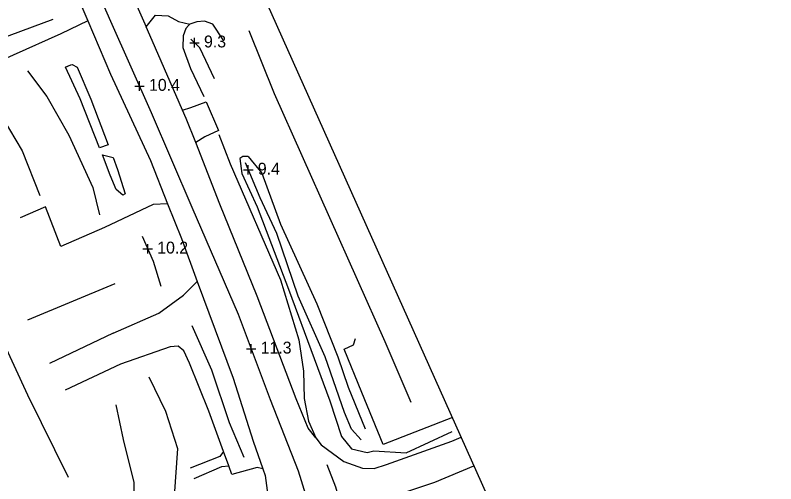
# Model space of a CAD drawing. Extents: x 2316231 to 2323598, y 363169 to 371906.
# Drawn here: x 2320994.3 to 2321314.7, y 364294.4 to 364491.7 of the extents above; entities that cross this region are included whole.
import ezdxf

# ---------------------------------------------------------------- set-up
doc = ezdxf.new("R2010")
doc.units = 0
for name, color, linetype in [('RD_DTM_BkLn1', 7, 'Continuous'), ('RD_DTM_TinHull', 7, 'Continuous'), ('RD_DTM_Void', 7, 'Continuous'), ('RD_EX_H2O', 7, 'Continuous'), ('RD_EX_Road', 7, 'Continuous')]:
    doc.layers.add(name, color=color, linetype=linetype)

msp = doc.modelspace()

# ---------------------------------------------------------------- linework, layer by layer
at = {"layer": 'RD_DTM_BkLn1'}
for p, q in [((2321036.254, 364378.524), (2320999.521, 364363.308)), ((2321035.573, 364357.804), (2321008.797, 364345.053)), ((2321038.693, 364344.812), (2321015.374, 364333.841))]:
    msp.add_line(p, q, dxfattribs=at)
for points in [[(2321019.52, 364523.148), (2321034.445, 364489.194), (2321051.599, 364450.752), (2321068.634, 364410.847), (2321088.233, 364365.793), (2321101.675, 364329.85), (2321113.518, 364299.79), (2321123.854, 364266.312), (2321127.765, 364245.259), (2321131.886, 364230.072), (2321137.453, 364206.087), (2321148.106, 364163.126), (2321158.282, 364114.755), (2321167.432, 364069.646)], [(2321010.188, 364489.799), (2320987.685, 364481.529), (2320972.647, 364474.751), (2320959.282, 364467.553), (2320948.373, 364463.615), (2320932.859, 364456.832), (2320927.564, 364454.539)], [(2321092.764, 364485.212), (2321103.411, 364458.659), (2321150.006, 364354.244), (2321160.92, 364328.735)], [(2320999.467, 364468.176), (2321007.551, 364457.429), (2321016.882, 364441.161), (2321026.969, 364419.106), (2321029.731, 364407.632)], [(2320981.896, 364460.068), (2320989.21, 364448.011), (2320997.168, 364434.55), (2321004.673, 364415.715)], [(2321092.46, 364432.146), (2321090.186, 364432.158), (2321088.852, 364431.393), (2321089.812, 364425.007), (2321096.237, 364410.976), (2321109.343, 364376.383), (2321120.198, 364347.124), (2321126.839, 364329.374), (2321131.736, 364314.306), (2321135.954, 364309.144), (2321142.573, 364307.564), (2321145.347, 364308.283), (2321158.932, 364307.428), (2321178.289, 364316.354)], [(2321092.46, 364432.146), (2321098.137, 364425.104), (2321106.018, 364403.678), (2321121.391, 364370.158), (2321130.222, 364347.777), (2321134.478, 364335.125), (2321141.718, 364317.592)], [(2320956.7, 364411.963), (2320969.866, 364394.944), (2320988.735, 364355.023), (2320999.519, 364331.909), (2321016.624, 364297.206)], [(2321047.821, 364398.681), (2321052.371, 364388.072), (2321055.577, 364377.603)], [(2321068.714, 364361.002), (2321076.973, 364342.429), (2321084.462, 364320.236), (2321090.58, 364305.601)], [(2321050.527, 364339.364), (2321057.529, 364324.907), (2321062.702, 364309.204), (2321061.198, 364289.188), (2321057.459, 364275.41)], [(2321036.709, 364327.601), (2321039.72, 364312.992), (2321044.201, 364294.954), (2321044.105, 364277.357)], [(2321125.55, 364302.496), (2321129.132, 364293.176), (2321132.928, 364280.066), (2321137.461, 364266.076), (2321140.912, 364255.306)], [(2321141.653, 364285.205), (2321171.004, 364295.118), (2321187.507, 364301.942)]]:
    msp.add_lwpolyline(points, dxfattribs=at)
at = {"layer": 'RD_DTM_TinHull'}
msp.add_lwpolyline([(2320809.363, 365353.877), (2320991.706, 364942.038), (2321080.196, 364541.654), (2321314.653, 364017.924), (2320828.919, 363723.372), (2320765.1, 363867.546), (2320638.089, 364094.01), (2320532.322, 364258.493), (2320402.792, 364459.125), (2320263.728, 364603.235), (2320177.718, 364755.167), (2319998.644, 364909.111), (2319975.332, 365147.552), (2319890.016, 365354.444)], dxfattribs=at)
at = {"layer": 'RD_DTM_Void'}
for p, q in [((2321069.812, 364478.095), (2321069.812, 364482.095)), ((2321067.812, 364480.095), (2321071.812, 364480.095)), ((2321044.654, 364461.834), (2321048.654, 364461.834)), ((2321046.654, 364459.834), (2321046.654, 364463.834)), ((2321090.485, 364426.535), (2321094.485, 364426.535)), ((2321092.485, 364424.535), (2321092.485, 364428.535)), ((2321050.114, 364391.335), (2321050.114, 364395.335)), ((2321048.114, 364393.335), (2321052.114, 364393.335)), ((2321093.68, 364349.227), (2321093.68, 364353.227)), ((2321091.68, 364351.227), (2321095.68, 364351.227))]:
    msp.add_line(p, q, dxfattribs=at)
at = {"layer": 'RD_EX_H2O'}
msp.add_line((2321068.365, 364481.468), (2321068.309, 364481.521), dxfattribs=at)
for points in [[(2321078.17, 364464.864), (2321072.11, 364477.914), (2321068.365, 364481.468)], [(2321140.062, 364312.95), (2321135.928, 364317.432), (2321132.929, 364324.397), (2321124.781, 364347.815), (2321113.511, 364373.389), (2321104.47, 364399.821), (2321097.498, 364414.719), (2321091.228, 364429.498)]]:
    msp.add_lwpolyline(points, dxfattribs=at)
at = {"layer": 'RD_EX_Road'}
for p, q in [((2321015.798, 364510.839), (2321024.89, 364489.308)), ((2321067.788, 364487.84), (2321067.259, 364487.28)), ((2321015.677, 364469.983), (2321017.682, 364470.704)), ((2321084.239, 364301.982), (2321082.048, 364307.973))]:
    msp.add_line(p, q, dxfattribs=at)
for points in [[(2321003.903, 364586.719), (2321005.682, 364582.579), (2321021.297, 364550.841), (2321034.078, 364521.338), (2321049.466, 364486.704)], [(2321049.466, 364486.704), (2321053.344, 364491.626), (2321058.687, 364491.423), (2321063.082, 364489.069), (2321067.788, 364487.84)], [(2321024.89, 364489.308), (2321013.465, 364483.866), (2320973.27, 364465.799), (2320951.752, 364457.335), (2320930.031, 364448.437)], [(2321024.89, 364489.308), (2321034.382, 364466.833), (2321051.223, 364430.468), (2321058.5, 364412.237)], [(2321067.259, 364487.28), (2321066.093, 364486.045), (2321064.997, 364482.966), (2321064.91, 364478.121), (2321068.153, 364469.283), (2321073.672, 364457.445)], [(2321081.819, 364481.275), (2321077.481, 364487.856), (2321074.035, 364489.112), (2321070.792, 364488.805), (2321067.788, 364487.84)], [(2321064.801, 364451.722), (2321051.999, 364481.002), (2321049.466, 364486.704)], [(2321017.682, 364470.704), (2321018.311, 364470.93), (2321020.414, 364469.814), (2321026.108, 364456.294), (2321033.512, 364437.067), (2321029.777, 364435.78), (2321021.587, 364456.471), (2321015.448, 364469.82), (2321017.682, 364470.704)], [(2321064.801, 364451.722), (2321068.23, 364452.838), (2321074.757, 364455.248), (2321079.938, 364443.141), (2321074.144, 364440.41), (2321070.326, 364438.004)], [(2321070.326, 364438.004), (2321066.336, 364448.212), (2321064.801, 364451.722)], [(2321080.094, 364441.428), (2321084.852, 364429.133), (2321106.011, 364380.317), (2321113.771, 364354.94), (2321115.781, 364341.799), (2321116.054, 364330.292), (2321117.774, 364320.728), (2321120.867, 364313.731)], [(2321120.867, 364313.731), (2321117.62, 364317.753), (2321112.576, 364330.216), (2321096.173, 364373.314), (2321080.454, 364412.091), (2321070.326, 364438.004)], [(2321031.018, 364432.855), (2321035.608, 364431.7), (2321037.387, 364426.707), (2321040.562, 364416.524), (2321039.635, 364415.848), (2321036.84, 364418.333), (2321034.35, 364424.361), (2321031.018, 364432.855)], [(2321058.5, 364412.237), (2321052.47, 364411.956), (2321031.934, 364402.322), (2321013.543, 364394.31), (2321007.041, 364411.01), (2320996.358, 364406.307)], [(2321058.5, 364412.237), (2321064.309, 364397.685), (2321070.999, 364379.624)], [(2321035.573, 364357.804), (2321054.815, 364366.16), (2321065.247, 364373.844), (2321070.999, 364379.624)], [(2321070.999, 364379.624), (2321086.086, 364338.893), (2321094.46, 364312.376), (2321098.546, 364300.647)], [(2321178.418, 364322.246), (2321149.246, 364310.913), (2321140.241, 364332.796), (2321132.834, 364351.082), (2321136.828, 364352.961), (2321137.608, 364355.616)], [(2321082.048, 364307.973), (2321075.843, 364324.943), (2321067.74, 364345.157), (2321065.274, 364350.434), (2321062.863, 364352.341), (2321059.513, 364352.096), (2321038.693, 364344.812)], [(2321120.867, 364313.731), (2321123.227, 364310.807), (2321132.775, 364303.8), (2321140.505, 364300.917), (2321145.422, 364300.887), (2321150.71, 364302.472), (2321178.155, 364312.296), (2321182.117, 364313.983)], [(2321082.048, 364307.973), (2321080.428, 364305.927), (2321068.027, 364300.988)], [(2321069.638, 364296.629), (2321081.266, 364301.651), (2321084.239, 364301.982)], [(2321098.546, 364300.647), (2321096.144, 364301.276), (2321085.595, 364298.273), (2321084.239, 364301.982)], [(2321098.546, 364300.647), (2321099.531, 364297.817), (2321100.687, 364289.464), (2321099.371, 364284.472), (2321096.859, 364279.915), (2321092.441, 364276.09), (2321084.055, 364270.541), (2321066.674, 364263.633)]]:
    msp.add_lwpolyline(points, dxfattribs=at)

# ---------------------------------------------------------------- texts
at = {"layer": 'RD_DTM_Void'}
for s, p in [('9.3', (2321073.812, 364478.095)), ('10.4', (2321050.654, 364459.834)), ('9.4', (2321096.485, 364424.535)), ('10.2', (2321054.114, 364391.335)), ('11.3', (2321097.68, 364349.227))]:
    msp.add_text(s, height=5, dxfattribs=at).set_placement(p)

doc.saveas('drawing.dxf')
